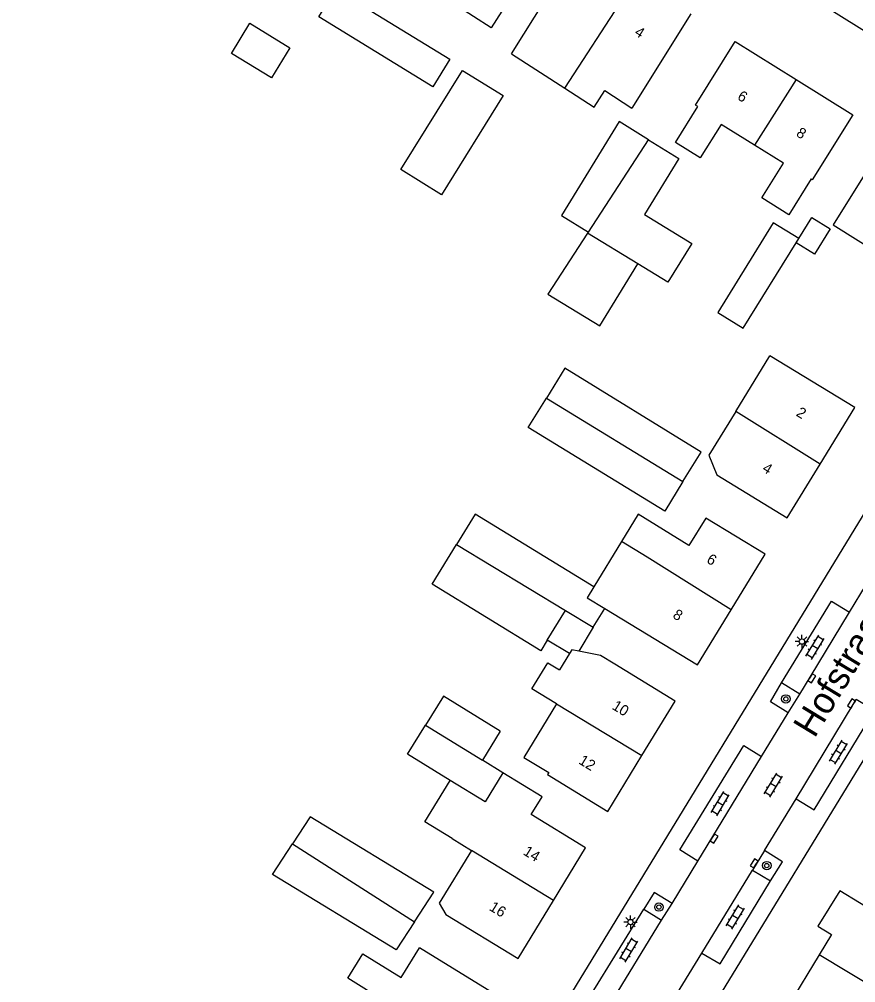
# Model space of a CAD drawing. Extents: x 136000 to 141014, y 402000 to 403500.
# Drawn here: x 137800.6 to 137879.3, y 402172.1 to 402262.7 of the extents above; entities that cross this region are included whole.
import ezdxf

# ---------------------------------------------------------------- set-up
doc = ezdxf.new("R2010")
doc.units = 0
for name, color, linetype in [('gg-anno-huisnummerreeks BGT', 7, 'Continuous'), ('gg-anno-openbare ruimte label', 7, 'Continuous'), ('gg-bbg-bijgebouw', 7, 'Continuous'), ('gg-bbg-gedigitaliseerde bebouwing', 7, 'Continuous'), ('gg-bbg-gedigitaliseerde bijgebouw', 7, 'Continuous'), ('gg-bbg-hoofdgebouw', 7, 'Continuous'), ('gg-bbg-luifel en loopbrug', 7, 'Continuous'), ('gg-bbg-tussenscheiding', 7, 'Continuous'), ('gg-knt-verharding', 7, 'Continuous'), ('gg-knt-verharding nz', 7, 'Continuous'), ('gt-bbg-plantopografie pand', 7, 'Continuous'), ('gt-symb-boom', 7, 'Continuous'), ('gt-symb-klinker verharding', 7, 'Continuous'), ('gt-symb-kolk', 7, 'Continuous'), ('gt-symb-lichtmast', 7, 'Continuous')]:
    doc.layers.add(name, color=color, linetype=linetype)

# ---------------------------------------------------------------- blocks, each defined once
blk = doc.blocks.new('gt0-KL1')
at = {"layer": 'gt-symb-klinker verharding'}
for p, q in [((-1.15, 0.3), (1.15, 0.3)), ((-1, -0.3), (-1, 0.3)), ((-0.5, 0.3), (-0.5, 0.45)), ((0, -0.3), (0, 0.3)), ((0.5, 0.3), (0.5, 0.45)), ((1, -0.3), (1, 0.3)), ((-1.15, -0.3), (1.15, -0.3)), ((-0.5, -0.45), (-0.5, -0.3)), ((0.5, -0.45), (0.5, -0.3))]:
    blk.add_line(p, q, dxfattribs=at)
blk = doc.blocks.new('gt0-KOLK')
at = {"layer": 'gt-symb-kolk'}
blk.add_lwpolyline([(0, 0), (0.375, 0), (0.375, 0.4), (-0.375, 0.4), (-0.375, 0), (0, 0)], dxfattribs=at)
blk = doc.blocks.new('gt0-BOOM')
at = {"layer": 'gt-symb-boom'}
for radius in [0.4, 0.2]:
    blk.add_circle((0, 0), radius, dxfattribs=at)
blk = doc.blocks.new('gt0-LMAST')
at = {"layer": 'gt-symb-lichtmast'}
for p, q in [((-0.182, 0.173), (-0.447, 0.438)), ((-0.005, 0.246), (-0.005, 0.621)), ((0.172, 0.173), (0.437, 0.438)), ((-0.255, -0.004), (-0.63, -0.004)), ((-0.182, -0.181), (-0.447, -0.446)), ((-0.005, -0.254), (-0.005, -0.629)), ((0.437, -0.446), (0.172, -0.181)), ((0.245, -0.004), (0.62, -0.004))]:
    blk.add_line(p, q, dxfattribs=at)
blk.add_circle((-0.005, -0.004), 0.25, dxfattribs=at)

msp = doc.modelspace()

# ---------------------------------------------------------------- linework, layer by layer
at = {"layer": 'gg-bbg-bijgebouw'}
msp.add_lwpolyline([(137842.339, 402257.912), (137846.161, 402255.534), (137840.359, 402246.208), (137836.537, 402248.586), (137842.339, 402257.912)], dxfattribs=at)
at = {"layer": 'gg-bbg-gedigitaliseerde bebouwing'}
for p, q in [((137846.939, 402259.471), (137853.35, 402269.75)), ((137863.79, 402263.23), (137858.265, 402254.366)), ((137846.939, 402259.471), (137851.939, 402256.229)), ((137868.03, 402225.815), (137871.243, 402231.047)), ((137879.22, 402226.19), (137871.243, 402231.047)), ((137866.264, 402219.849), (137872.88, 402215.79)), ((137857.293, 402213.587), (137854.678, 402209.304)), ((137855.702, 402207.288), (137864.43, 402201.96)), ((137852.394, 402203.029), (137851.455, 402201.494)), ((137862.34, 402198.56), (137856.663, 402202.025)), ((137853.91, 402184.75), (137848.786, 402187.871)), ((137841.342, 402185.619), (137843.166, 402184.506)), ((137840.769, 402178.486), (137847.56, 402174.35)), ((137845.47, 402170.93), (137838.264, 402175.341))]:
    msp.add_line(p, q, dxfattribs=at)
for points in [[(137851.939, 402256.229), (137854.698, 402254.441), (137855.718, 402256.016), (137858.265, 402254.366)], [(137879.03, 402253.72), (137875.222, 402247.627), (137875.119, 402247.692), (137873.018, 402244.33), (137870.494, 402245.907), (137872.53, 402249.166), (137869.799, 402250.873)], [(137869.799, 402250.873), (137866.666, 402252.83), (137864.691, 402249.669), (137862.352, 402251.13)], [(137881.82, 402250.8), (137877.182, 402243.383), (137881.657, 402240.582), (137883.235, 402242.989), (137885.049, 402241.781), (137883.528, 402239.461), (137887.71, 402236.72)], [(137868.03, 402225.815), (137865.505, 402221.704), (137866.264, 402219.849)], [(137863.628, 402213.206), (137858.857, 402216.136), (137857.293, 402213.587)], [(137870.79, 402212.38), (137865.204, 402215.788), (137863.628, 402213.206)], [(137853.254, 402203.248), (137852.603, 402203.372), (137852.394, 402203.029)], [(137856.663, 402202.025), (137855.298, 402202.859), (137853.254, 402203.248)], [(137851.152, 402198.299), (137848.832, 402199.704), (137850.349, 402202.173), (137851.455, 402201.494)], [(137851.152, 402198.299), (137848.109, 402193.264), (137850.446, 402191.852)], [(137848.786, 402187.871), (137849.818, 402189.563), (137846.131, 402191.814)], [(137850.446, 402191.852), (137850.318, 402191.642), (137855.99, 402188.17)], [(137841.342, 402185.619), (137838.782, 402187.182), (137841.169, 402191.092)], [(137843.166, 402184.506), (137840.14, 402179.551), (137840.769, 402178.486)], [(137835.146, 402170.234), (137831.542, 402172.481), (137832.941, 402174.772), (137836.565, 402172.559), (137838.264, 402175.341)]]:
    msp.add_lwpolyline(points, dxfattribs=at)
at = {"layer": 'gg-bbg-gedigitaliseerde bijgebouw'}
for p, q in [((137854.165, 402242.698), (137854.088, 402242.58)), ((137850.299, 402204.281), (137852.029, 402207.097)), ((137852.029, 402207.097), (137854.621, 402205.505)), ((137854.621, 402205.505), (137855.702, 402207.288)), ((137845.873, 402195.742), (137844.192, 402193.005)), ((137846.131, 402191.814), (137844.192, 402193.005))]:
    msp.add_line(p, q, dxfattribs=at)
for points in [[(137828.823, 402262.95), (137830.422, 402265.553), (137841.122, 402258.982), (137839.523, 402256.379), (137828.823, 402262.95)], [(137820.594, 402259.511), (137822.333, 402262.345), (137826.08, 402260.046), (137824.341, 402257.211), (137820.594, 402259.511)], [(137859.835, 402251.385), (137857.052, 402253.094), (137851.626, 402244.258), (137854.165, 402242.698)], [(137859.835, 402251.385), (137862.688, 402249.633), (137859.443, 402244.349), (137863.885, 402241.621), (137861.646, 402237.975), (137858.831, 402239.704)], [(137873.953, 402242.078), (137871.545, 402243.556), (137866.36, 402235.114), (137868.713, 402233.669), (137873.702, 402241.674)], [(137873.953, 402242.078), (137875.195, 402244.069), (137876.911, 402243.015), (137875.434, 402240.61), (137873.702, 402241.674)], [(137854.088, 402242.58), (137850.357, 402236.864), (137855.244, 402233.863), (137858.831, 402239.704)], [(137863.063, 402219.214), (137864.774, 402221.999), (137851.937, 402229.882), (137850.214, 402227.077)], [(137863.063, 402219.214), (137861.353, 402216.428), (137848.516, 402224.312), (137850.214, 402227.077)], [(137854.678, 402209.304), (137843.511, 402216.163), (137841.754, 402213.302)], [(137850.299, 402204.281), (137849.684, 402203.28), (137839.456, 402209.561), (137841.754, 402213.302)], [(137845.873, 402195.742), (137840.527, 402199.025), (137838.846, 402196.288)], [(137841.169, 402191.092), (137837.165, 402193.551), (137838.846, 402196.288)], [(137837.802, 402177.791), (137839.621, 402180.59), (137828.008, 402187.681), (137826.344, 402185.121)], [(137837.802, 402177.791), (137836.077, 402175.137), (137824.464, 402182.228), (137826.344, 402185.121)]]:
    msp.add_lwpolyline(points, dxfattribs=at)
at = {"layer": 'gg-bbg-hoofdgebouw'}
for p, q in [((137867.97, 402260.63), (137873.702, 402257.049)), ((137873.702, 402257.049), (137879.03, 402253.72)), ((137875.966, 402220.853), (137879.22, 402226.19)), ((137872.88, 402215.79), (137875.966, 402220.853)), ((137867.605, 402207.161), (137870.79, 402212.38)), ((137864.43, 402201.96), (137867.605, 402207.161)), ((137859.206, 402193.432), (137862.34, 402198.56)), ((137855.99, 402188.17), (137859.206, 402193.432)), ((137850.884, 402179.794), (137853.91, 402184.75)), ((137847.56, 402174.35), (137850.884, 402179.794)), ((137877.053, 402176.597), (137875.886, 402174.682)), ((137875.886, 402174.682), (137872.71, 402169.47))]:
    msp.add_line(p, q, dxfattribs=at)
for points in [[(137862.352, 402251.13), (137864.456, 402254.508), (137864.247, 402254.638), (137867.97, 402260.63)], [(137883.357, 402177.304), (137877.811, 402180.717), (137875.765, 402177.382), (137877.053, 402176.597)]]:
    msp.add_lwpolyline(points, dxfattribs=at)
at = {"layer": 'gg-bbg-luifel en loopbrug'}
for p, q in [((137854.621, 402205.505), (137853.254, 402203.248)), ((137852.394, 402203.029), (137850.299, 402204.281))]:
    msp.add_line(p, q, dxfattribs=at)
at = {"layer": 'gg-bbg-tussenscheiding'}
for p, q in [((137851.939, 402256.229), (137859.308, 402267.598)), ((137873.702, 402257.049), (137869.799, 402250.873)), ((137854.165, 402242.698), (137859.835, 402251.385)), ((137858.831, 402239.704), (137854.088, 402242.58)), ((137873.702, 402241.674), (137873.953, 402242.078)), ((137850.214, 402227.077), (137863.063, 402219.214)), ((137875.966, 402220.853), (137868.03, 402225.815)), ((137841.754, 402213.302), (137852.029, 402207.097)), ((137851.152, 402198.299), (137859.206, 402193.432)), ((137838.846, 402196.288), (137844.192, 402193.005)), ((137826.344, 402185.121), (137837.802, 402177.791)), ((137850.884, 402179.794), (137843.166, 402184.506)), ((137881.613, 402171.208), (137875.886, 402174.682))]:
    msp.add_line(p, q, dxfattribs=at)
for points in [[(137867.605, 402207.161), (137859.684, 402212.1), (137857.293, 402213.587)], [(137854.678, 402209.304), (137854.06, 402208.291), (137855.702, 402207.288)], [(137846.131, 402191.814), (137844.45, 402189.077), (137841.169, 402191.092)]]:
    msp.add_lwpolyline(points, dxfattribs=at)
at = {"layer": 'gg-knt-verharding'}
for p, q in [((137900.184, 402249.164), (137826.33, 402128.07)), ((137840.648, 402128.477), (137908.81, 402240.12)), ((137878.721, 402206.931), (137882.392, 402212.976)), ((137874.046, 402199.225), (137872.348, 402200.266)), ((137872.976, 402197.458), (137874.046, 402199.225)), ((137870.46, 402193.34), (137872.976, 402197.458)), ((137870.733, 402184.491), (137873.7, 402189.351)), ((137870.733, 402184.491), (137869.604, 402182.645)), ((137862.034, 402179.513), (137864.468, 402183.492)), ((137869.604, 402182.645), (137871.307, 402181.629)), ((137859.375, 402178.982), (137861.06, 402177.953)), ((137861.06, 402177.953), (137862.034, 402179.513)), ((137861.794, 402169.86), (137864.843, 402174.852))]:
    msp.add_line(p, q, dxfattribs=at)
for points in [[(137796.264, 402314.159), (137829.568, 402293.147), (137877.981, 402262.977), (137900.184, 402249.164)], [(137872.348, 402200.266), (137877.035, 402207.965), (137878.721, 402206.931)], [(137872.976, 402197.458), (137871.289, 402198.483), (137872.348, 402200.266)], [(137873.7, 402189.351), (137875.399, 402188.323), (137881.078, 402197.666), (137879.353, 402198.698)], [(137864.468, 402183.492), (137862.769, 402184.547), (137868.776, 402194.388), (137870.46, 402193.34)], [(137871.307, 402181.629), (137872.433, 402183.433), (137870.733, 402184.491)], [(137864.843, 402174.852), (137866.558, 402173.841), (137871.307, 402181.629)], [(137862.034, 402179.513), (137860.357, 402180.554), (137859.375, 402178.982)], [(137856.128, 402169.905), (137854.415, 402170.938), (137859.375, 402178.982)]]:
    msp.add_lwpolyline(points, dxfattribs=at)
at = {"layer": 'gg-knt-verharding nz'}
for p, q in [((137864.468, 402183.492), (137870.46, 402193.34)), ((137864.843, 402174.852), (137869.604, 402182.645)), ((137856.128, 402169.905), (137861.06, 402177.953))]:
    msp.add_line(p, q, dxfattribs=at)
for points in [[(137874.046, 402199.225), (137875.022, 402200.814), (137878.721, 402206.931)], [(137873.7, 402189.351), (137879.085, 402198.229), (137879.353, 402198.698)]]:
    msp.add_lwpolyline(points, dxfattribs=at)
at = {"layer": 'gt-bbg-plantopografie pand'}
msp.add_lwpolyline([(137839.143, 402282.464), (137847.521, 402277.235), (137846.525, 402275.639), (137851.709, 402272.403), (137845.032, 402261.931), (137841.686, 402264.065), (137844.498, 402268.474), (137842.378, 402269.826), (137842.594, 402270.166), (137838.444, 402272.812), (137833.651, 402265.295), (137834.042, 402265.046), (137833.793, 402264.655), (137829.525, 402267.21)], dxfattribs=at)

# ---------------------------------------------------------------- block references
at = {"layer": 'gt-symb-boom'}
for p in [(137872.745, 402198.763), (137870.949, 402183.078), (137860.805, 402179.176)]:
    msp.add_blockref('gt0-BOOM', p, dxfattribs=at)
at = {"layer": 'gt-symb-klinker verharding'}
for p, rotation in [((137875.489, 402203.625), 58.53512697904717), ((137877.695, 402193.748), 58.91827016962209), ((137871.566, 402190.649), 58.99693247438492), ((137866.574, 402188.899), 58.94783928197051), ((137867.988, 402178.233), 58.91827016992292), ((137857.962, 402175.129), 58.91827016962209)]:
    msp.add_blockref('gt0-KL1', p, dxfattribs=dict(at, rotation=rotation))
at = {"layer": 'gt-symb-kolk'}
for p, rotation in [((137875.022, 402200.814), -121.59249156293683), ((137879.085, 402198.229), 58.741514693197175), ((137865.825, 402185.722), -121.33720572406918), ((137869.932, 402183.179), 58.61387523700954)]:
    msp.add_blockref('gt0-KOLK', p, dxfattribs=dict(at, rotation=rotation))
at = {"layer": 'gt-symb-lichtmast'}
for p in [(137874.265, 402204.164), (137858.129, 402177.766)]:
    msp.add_blockref('gt0-LMAST', p, dxfattribs=at)

# ---------------------------------------------------------------- texts
at = {"layer": 'gg-anno-huisnummerreeks BGT'}
for s, rotation, p in [('4', 327.9, (137858.424, 402261.281)), ('6', 328, (137868.104, 402255.241)), ('8', 328, (137873.633, 402251.786)), ('2', 328.6, (137873.633, 402225.457)), ('4', 328.7, (137870.446, 402220.229)), ('6', 328.6, (137865.203, 402211.648)), ('8', 328.6, (137862.023, 402206.438)), ('10', 328.6, (137856.313, 402197.858)), ('12', 328.6, (137853.174, 402192.722)), ('14', 328.6, (137847.955, 402184.164)), ('16', 328.6, (137844.761, 402178.933))]:
    msp.add_text(s, height=1, rotation=rotation, dxfattribs=at).set_placement(p)
at = {"layer": 'gg-anno-openbare ruimte label'}
msp.add_text('Hofstraat', height=2.5, rotation=58.7, dxfattribs=at).set_placement((137875.44, 402194.992))

doc.saveas('drawing.dxf')
